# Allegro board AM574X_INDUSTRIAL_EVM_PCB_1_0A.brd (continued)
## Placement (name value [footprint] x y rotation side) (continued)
Q27  MMBT2907A  [SOT23-3-44M]  113.41 128.27 180 bottom
R1_1  DNI  [SM-7351-RES-0603]  179.31 7.63 90 top
R2  10K  [SM-7351-RES-0402]  127.89 64.85 0 top
R2_1  DNI  [SM-7351-RES-0402]  172.7 6.49 180 top
R3  22.1  [SM-7351-RES-0402]  182.02 96.6 0 bottom
R4  1M  [SM-7351-RES-0402]  77.6 82.38 270 top
R5  0  [SM-7351-RES-0402]  79.25 82.76 180 top
R6  0  [SM-7351-RES-0402]  133.73 74.07 0 top
R7  0  [SM-7351-RES-0402]  124.08 65.49 0 top
R8  0  [SM-7351-RES-0402]  124.08 69.3 0 top
R9  0  [SM-7351-RES-0402]  136.91 126.45 180 bottom
R10  10K  [SM-7351-RES-0402]  170.05 45.76 180 bottom
R11  100  [SM-7351-RES-0402]  168.15 53.55 0 bottom
R13  0  [SM-7351-RES-0402]  69.74 82.33 180 top
R14  0  [SM-7351-RES-0402]  130.43 114.76 270 top
R15  0  [SM-7351-RES-0402]  132.72 114.76 270 top
R16  1K  [SM-7351-RES-0402]  134.49 122.38 180 bottom
R17  1K  [SM-7351-RES-0402]  137.13 122.3 180 bottom
R18  10K  [SM-7351-RES-0402]  144.54 126.96 90 bottom
R19  0  [SM-7351-RES-0402]  142.49 140.54 90 top
R20  0  [SM-7351-RES-0402]  142.88 135.97 90 top
R21  1K  [SM-7351-RES-0402]  138.94 128.35 270 bottom
R22  10K  [SM-7351-RES-0402]  89.79 108.79 270 top
R23  0  [SM-7351-RES-0402]  101.85 112.48 270 top
R24  0  [SM-7351-RES-0402]  101.98 99.78 270 top
R25  0  [SM-7351-RES-0402]  98.68 108.79 270 top
R26  0  [SM-7351-RES-0402]  91.06 124.16 90 top
R27  0  [SM-7351-RES-0402]  91.06 108.79 270 top
R28  0  [SM-7351-RES-0402]  101.35 124.16 90 top
R29  0  [SM-7351-RES-0402]  97.41 124.16 90 top
R30  0  [SM-7351-RES-0402]  92.33 124.16 90 top
R31  0  [SM-7351-RES-0402]  101.85 114.51 270 top
R32  10K  [SM-7351-RES-0402]  124.71 40.51 0 top
R33  10K  [SM-7351-RES-0402]  108.84 40.51 180 top
R34  10K  [SM-7351-RES-0402]  124.71 38.48 0 top
R35  10K  [SM-7351-RES-0402]  108.84 39.5 180 top
R36  18.2K  [SM-7351-RES-0402]  124.59 42.75 180 top
R37  10K  [SM-7351-RES-0402]  124.71 39.5 0 top
R38  10K  [SM-7351-RES-0402]  108.84 37.46 180 top
R39  10K  [SM-7351-RES-0402]  124.71 37.46 0 top
R40  10K  [SM-7351-RES-0402]  108.84 38.48 180 top
R41  240  [SM-7351-RES-0402]  93.6 30.1 180 top
R42  240  [SM-7351-RES-0402]  124.08 30.1 180 top
R44  240  [SM-7351-RES-0402]  108.84 30.1 180 top
R45  10K  [SM-7351-RES-0402]  111.12 15.11 0 top
R46  49.9  [SM-7351-RES-0402]  127.51 31.5 180 bottom
R47  49.9  [SM-7351-RES-0402]  127.51 30.48 180 bottom
R48  10K  [SM-7351-RES-0402]  111.12 13.97 180 top
R49  47  [SM-7351-RES-0402]  124.08 29.59 180 bottom
R50  47  [SM-7351-RES-0402]  108.84 26.42 0 top
R51  47  [SM-7351-RES-0402]  108.71 30.35 0 bottom
R52  47  [SM-7351-RES-0402]  108.71 27.81 0 bottom
R53  47  [SM-7351-RES-0402]  117.22 21.72 90 bottom
R54  47  [SM-7351-RES-0402]  118.24 21.72 90 bottom
R55  47  [SM-7351-RES-0402]  119.25 21.72 90 bottom
R56  100K  [SM-7351-RES-0402]  108.2 11 270 top
R57  47  [SM-7351-RES-0402]  116.46 21.72 90 top
R58  47  [SM-7351-RES-0402]  114.17 21.72 90 bottom
R59  47  [SM-7351-RES-0402]  124.08 26.29 180 top
R60  47  [SM-7351-RES-0402]  116.2 21.72 90 bottom
R61  47  [SM-7351-RES-0402]  124.08 25.02 180 bottom
R62  47  [SM-7351-RES-0402]  113.16 21.72 90 top
R63  47  [SM-7351-RES-0402]  120.27 21.72 90 top
R64  47  [SM-7351-RES-0402]  114.17 21.72 90 top
R65  47  [SM-7351-RES-0402]  117.47 21.72 90 top
R66  47  [SM-7351-RES-0402]  124.08 31.88 180 top
R67  0  [SM-7351-RES-0402]  106.3 11.51 180 top
R68  47  [SM-7351-RES-0402]  121.54 21.72 90 bottom
R69  10  [SM-7351-RES-0402]  104.65 17.4 180 top
R70  47  [SM-7351-RES-0402]  115.32 21.72 90 top
R71  47  [SM-7351-RES-0402]  118.49 21.72 90 top
R72  47  [SM-7351-RES-0402]  115.19 21.72 90 bottom
R73  47  [SM-7351-RES-0402]  124.08 27.56 180 top
R74  47  [SM-7351-RES-0402]  120.4 21.72 90 bottom
R75  47  [SM-7351-RES-0402]  108.84 27.56 0 top
R76  2.2K  [SM-7351-RES-0402]  25.91 121.11 0 bottom
R77  0  [SM-7351-RES-0402]  22.48 136.48 90 bottom
R78  0  [SM-7351-RES-0402]  7.75 141.69 180 bottom
R79  DNI  [SM-7351-RES-0402]  38.25 110.75 90 top
R80  DNI  [SM-7351-RES-0402]  32.66 110.75 90 top
R81  DNI  [SM-7351-RES-0402]  35.46 110.75 90 top
R82  DNI  [SM-7351-RES-0402]  36.86 110.75 90 top
R83  0  [SM-7351-RES-0402]  24.77 112.73 270 bottom
R84  DNI  [SM-7351-RES-0402]  34.06 110.75 90 top
R85  DNI  [SM-7351-RES-0402]  31.27 110.75 90 top
R86  0  [SM-7351-RES-0402]  23.68 112.73 270 bottom
R87  DNI  [SM-7351-RES-0402]  87.38 102.19 90 top
R88  DNI  [SM-7351-RES-0402]  86.11 102.19 90 top
R89  0  [SM-7351-RES-0402]  7.24 119.72 180 bottom
R90  DNI  [SM-7351-RES-0402]  91.19 102.19 90 top
R91  DNI  [SM-7351-RES-0402]  89.92 102.19 90 top
R92  DNI  [SM-7351-RES-0402]  84.84 102.19 90 top
R93  0  [SM-7351-RES-0402]  6.48 132.03 270 bottom
R94  DNI  [SM-7351-RES-0402]  88.65 102.19 90 top
R95  DNI  [SM-7351-RES-0402]  22.86 110.7 270 bottom
R96  0  [SM-7351-RES-0402]  25.91 118.83 0 bottom
R97  0  [SM-7351-RES-0603]  23.49 123.78 270 top
R98  0  [SM-7351-RES-0402]  25.91 119.84 0 bottom
R99  49.9  [SM-7351-RES-0402]  17.84 123.53 0 bottom
R100  49.9  [SM-7351-RES-0402]  19.87 123.53 180 bottom
R101  49.9  [SM-7351-RES-0402]  22.61 127.21 90 bottom
R102  49.9  [SM-7351-RES-0402]  22.61 129.24 270 bottom
R103  4.87K  [SM-7351-RES-0402]  23.49 121.11 180 top
R104  2.2K  [SM-7351-RES-0402]  22.03 113.11 90 bottom
R105  DNI  [SM-7351-RES-0402]  86.11 114.13 270 top
R106  0  [SM-7351-RES-0402]  6.48 129.88 90 bottom
R107  10K  [SM-7351-RES-0402]  43.05 86.82 270 bottom
R108  2.2K  [SM-7351-RES-0402]  17.53 115.78 90 bottom
R109  2.2K  [SM-7351-RES-0402]  18.73 114.25 90 bottom
R110  2.2K  [SM-7351-RES-0402]  19.87 114.25 90 bottom
R111  2.2K  [SM-7351-RES-0402]  21.02 114.25 90 bottom
R112  0  [SM-7351-RES-0402]  44.7 87.33 0 bottom
R113  62  [SM-7351-RES-0402]  140.34 14.86 180 top
R114  0  [SM-7351-RES-0402]  141.61 10.41 0 top
R115  0  [SM-7351-RES-0402]  43.43 83.14 90 top
R116  2.2K  [SM-7351-RES-0402]  141.61 11.43 0 top
R117  0  [SM-7351-RES-0402]  45.97 83.14 90 top
R118  0  [SM-7351-RES-0402]  48.51 83.14 90 top
R119  0  [SM-7351-RES-0402]  51.05 83.14 90 top
R120  2.2K  [SM-7351-RES-0402]  29.59 93.17 270 top
R121  0  [SM-7351-RES-0402]  23.37 99.27 270 bottom
R122  0  [SM-7351-RES-0402]  7.7 117.55 180 bottom
R123  DNI  [SM-7351-RES-0402]  114.68 99.78 270 top
R124  DNI  [SM-7351-RES-0402]  118.49 99.9 270 top
R125  DNI  [SM-7351-RES-0402]  114.55 103.84 90 top
R126  DNI  [SM-7351-RES-0402]  119.63 103.84 90 top
R127  DNI  [SM-7351-RES-0402]  116.08 99.78 270 top
R128  DNI  [SM-7351-RES-0402]  117.47 99.9 270 top
R129  DNI  [SM-7351-RES-0402]  118.36 103.84 90 top
R130  DNI  [SM-7351-RES-0402]  117.09 103.84 90 top
R131  2.2K  [SM-7351-RES-0402]  27.69 95.33 270 top
R132  DNI  [SM-7351-RES-0402]  52.58 109.56 90 top
R133  DNI  [SM-7351-RES-0402]  58.17 109.56 90 top
R134  0  [SM-7351-RES-0402]  7.19 95.58 180 bottom
R135  DNI  [SM-7351-RES-0402]  59.56 109.56 90 top
R136  DNI  [SM-7351-RES-0402]  120.9 103.84 90 top
R137  DNI  [SM-7351-RES-0402]  115.82 103.84 90 top
R138  0  [SM-7351-RES-0603]  6.48 108.67 270 bottom
R139  DNI  [SM-7351-RES-0402]  56.77 109.56 90 top
R140  0  [SM-7351-RES-0402]  30.61 95.33 270 top
R141  0  [SM-7351-RES-0603]  29.34 101.55 270 bottom
R142  0  [SM-7351-RES-0402]  29.59 95.33 270 top
R143  49.9  [SM-7351-RES-0402]  24.38 106.89 270 top
R144  49.9  [SM-7351-RES-0402]  24.38 104.86 90 top
R145  49.9  [SM-7351-RES-0402]  24.38 102.82 270 top
R146  49.9  [SM-7351-RES-0402]  24.38 100.67 90 top
R147  4.87K  [SM-7351-RES-0402]  26.03 97.74 0 top
R148  DNI  [SM-7351-RES-0402]  55.37 109.56 90 top
R149  10K  [SM-7351-RES-0402]  186.72 83.14 180 bottom
R150  DNI  [SM-7351-RES-0402]  53.98 109.56 90 top
R151  0  [SM-7351-RES-0402]  6.43 105.74 90 bottom
R152  2.2K  [SM-7351-RES-0402]  37.39 100.16 0 top
R153  10K  [SM-7351-RES-0402]  33.15 89.74 90 bottom
R154  0  [SM-7351-RES-0402]  34.8 89.24 0 bottom
R155  2.2K  [SM-7351-RES-0402]  37.34 104.73 180 top
R156  2.2K  [SM-7351-RES-0402]  37.34 103.59 180 top
R157  2.2K  [SM-7351-RES-0402]  37.34 102.44 180 top
R158  2.2K  [SM-7351-RES-0402]  37.34 101.3 180 top
R159  2.2K  [SM-7351-RES-0402]  28.19 77.55 270 top
R160  0  [SM-7351-RES-0402]  23.37 75.14 270 bottom
R161  0  [SM-7351-RES-0402]  7.75 93.43 180 bottom
R162  0  [SM-7351-RES-0402]  124.08 82.76 180 top
R163  0  [SM-7351-RES-0402]  124.08 81.62 180 top
R164  0  [SM-7351-RES-0402]  124.08 83.9 180 top
R165  0  [SM-7351-RES-0402]  37.34 77.68 0 top
R166  0  [SM-7351-RES-0402]  37.34 78.82 0 top
R167  0  [SM-7351-RES-0402]  120.27 84.54 180 top
R168  0  [SM-7351-RES-0402]  120.27 82.25 180 top
R169  0  [SM-7351-RES-0402]  124.08 85.17 180 top
R170  0  [SM-7351-RES-0402]  37.34 81.11 0 top
R171  0  [SM-7351-RES-0402]  37.34 83.52 0 bottom
R172  0  [SM-7351-RES-0402]  7.24 71.46 180 bottom
R173  0  [SM-7351-RES-0402]  37.34 84.66 0 bottom
R174  0  [SM-7351-RES-0402]  37.34 85.81 0 bottom
R175  0  [SM-7351-RES-0402]  37.34 86.95 0 bottom
R176  0  [SM-7351-RES-0402]  6.48 83.77 270 bottom
R177  0  [SM-7351-RES-0402]  37.34 79.96 0 top
R178  0  [SM-7351-RES-0402]  124.08 80.35 180 top
R179  0  [SM-7351-RES-0402]  30.61 77.55 270 top
R180  0  [SM-7351-RES-0603]  29.34 83.77 270 bottom
R181  0  [SM-7351-RES-0402]  29.59 77.55 270 top
R182  49.9  [SM-7351-RES-0402]  24.38 89.11 270 top
R183  49.9  [SM-7351-RES-0402]  24.38 87.08 90 top
R184  49.9  [SM-7351-RES-0402]  24.38 85.04 270 top
R185  49.9  [SM-7351-RES-0402]  24.38 82.89 90 top
R186  4.87K  [SM-7351-RES-0402]  28.19 77.55 90 bottom
R187  2.2K  [SM-7351-RES-0402]  37.34 82.5 180 top
R188  0  [SM-7351-RES-0402]  120.27 78.06 180 top
R189  0  [SM-7351-RES-0402]  6.48 81.62 90 bottom
R190  10K  [SM-7351-RES-0402]  28.19 71.2 90 bottom
R191  2.2K  [SM-7351-RES-0402]  37.34 86.95 180 top
R192  2.2K  [SM-7351-RES-0402]  37.34 85.81 180 top
R193  2.2K  [SM-7351-RES-0402]  37.34 84.66 180 top
R194  2.2K  [SM-7351-RES-0402]  37.34 83.52 180 top
R195  0  [SM-7351-RES-0402]  29.84 70.69 0 bottom
R196  0  [SM-7351-RES-0402]  43.31 74.5 90 top
R197  0  [SM-7351-RES-0402]  45.85 74.5 90 top
R198  0  [SM-7351-RES-0402]  48.39 74.5 90 top
R199  0  [SM-7351-RES-0402]  50.93 74.5 90 top
R200  2.2K  [SM-7351-RES-0402]  28.19 52.79 270 top
R201  2.2K  [SM-7351-RES-0402]  29.59 50.63 270 top
R202  0  [SM-7351-RES-0402]  23.37 50.37 270 bottom
R203  0  [SM-7351-RES-0402]  7.75 68.66 180 bottom
R204  0  [SM-7351-RES-0402]  78.36 95.97 0 top
R205  0  [SM-7351-RES-0402]  78.36 98 0 top
R206  0  [SM-7351-RES-0402]  78.36 94.95 0 top
R207  0  [SM-7351-RES-0402]  78.36 93.93 0 top
R208  0  [SM-7351-RES-0402]  78.36 92.92 0 top
R209  0  [SM-7351-RES-0402]  37.34 52.91 0 top
R210  0  [SM-7351-RES-0402]  78.36 96.98 0 top
R211  0  [SM-7351-RES-0402]  37.34 54.06 0 top
R212  0  [SM-7351-RES-0402]  37.34 56.34 0 top
R213  0  [SM-7351-RES-0402]  37.34 58.76 0 bottom
R214  0  [SM-7351-RES-0402]  7.24 46.69 180 bottom
R215  0  [SM-7351-RES-0402]  37.34 59.9 0 bottom
R216  0  [SM-7351-RES-0402]  37.34 61.04 0 bottom
R217  0  [SM-7351-RES-0402]  37.34 62.18 0 bottom
R218  0  [SM-7351-RES-0603]  6.48 59.39 270 bottom
R219  0  [SM-7351-RES-0402]  37.34 55.2 0 top
R220  DNI  [SM-7351-RES-0402]  124.08 74.76 180 top
R221  0  [SM-7351-RES-0402]  30.61 52.79 270 top
R222  0  [SM-7351-RES-0603]  29.34 59.01 270 bottom
R223  0  [SM-7351-RES-0402]  29.59 52.79 270 top
R224  49.9  [SM-7351-RES-0402]  24.38 64.34 270 top
R225  49.9  [SM-7351-RES-0402]  24.38 62.31 90 top
R226  49.9  [SM-7351-RES-0402]  24.38 60.28 270 top
R227  49.9  [SM-7351-RES-0402]  24.38 58.12 90 top
R228  4.87K  [SM-7351-RES-0402]  28.19 52.79 90 bottom
R230  0  [SM-7351-RES-0402]  124.08 77.17 180 top
R231  0  [SM-7351-RES-0402]  6.48 56.6 270 bottom
R232  2.2K  [SM-7351-RES-0402]  37.34 57.74 0 bottom
R233  10K  [SM-7351-RES-0402]  28.19 46.44 90 bottom
R234  0  [SM-7351-RES-0402]  29.84 45.93 0 bottom
R235  2.2K  [SM-7351-RES-0402]  37.34 62.18 180 top
R236  2.2K  [SM-7351-RES-0402]  37.34 61.04 180 top
R237  2.2K  [SM-7351-RES-0402]  37.34 59.9 180 top
R238  2.2K  [SM-7351-RES-0402]  37.34 58.76 180 top
R239  220  [SM-7351-RES-0402]  9.53 4.7 180 bottom
R240  220  [SM-7351-RES-0402]  16.13 4.7 180 bottom
R241  0  [SM-7351-RES-0402]  9.53 3.64 180 bottom
R242  220  [SM-7351-RES-0402]  9.53 11.43 180 bottom
R243  0  [SM-7351-RES-0402]  16.13 3.64 180 bottom
R244  220  [SM-7351-RES-0402]  16.13 11.43 180 bottom
R245  100K  [SM-7351-RES-0402]  9.53 2.62 0 bottom
R246  100K  [SM-7351-RES-0402]  16.13 2.62 0 bottom
R247  0  [SM-7351-RES-0402]  9.53 10.37 0 bottom
R248  0  [SM-7351-RES-0402]  16.13 10.37 0 bottom
R249  220  [SM-7351-RES-0402]  9.53 8 180 bottom
R250  220  [SM-7351-RES-0402]  16.13 8 180 bottom
R251  100K  [SM-7351-RES-0402]  9.53 9.35 0 bottom
R252  100K  [SM-7351-RES-0402]  16.13 9.35 0 bottom
R253  0  [SM-7351-RES-0402]  9.53 6.94 0 bottom
R254  0  [SM-7351-RES-0402]  16.13 6.94 0 bottom
R255  100K  [SM-7351-RES-0402]  9.53 5.92 0 bottom
R256  100K  [SM-7351-RES-0402]  16.13 5.92 0 bottom
R257  0  [SM-7351-RES-0402]  159 142.83 270 top
R258  0  [SM-7351-RES-0402]  162.71 133.56 90 top
R259  10K  [SM-7351-RES-0402]  177.95 133.56 270 bottom
R260  0  [SM-7351-RES-0402]  161.54 142.83 90 top
R261  0  [SM-7351-RES-0402]  164.11 133.56 270 top
R262  0  [SM-7351-RES-0402]  165.38 133.56 90 top
R263  0  [SM-7351-RES-0402]  166.65 133.56 270 top
R264  0  [SM-7351-RES-0402]  167.79 133.56 90 top
R265  0  [SM-7351-RES-0402]  169.19 133.56 270 top
R267  0  [SM-7351-RES-0402]  174.27 133.56 270 top
R269  0  [SM-7351-RES-0402]  176.81 133.56 270 top
R271  0  [SM-7351-RES-0402]  179.35 133.56 270 top
R273  0  [SM-7351-RES-0402]  181.89 133.56 270 top
R274  0  [SM-7351-RES-0402]  180.62 133.56 90 top
R275  0  [SM-7351-RES-0402]  185.57 133.56 90 top
R276  22.1  [SM-7351-RES-0402]  163.83 144.02 0 bottom
R277  0  [SM-7351-RES-0402]  188.11 133.56 90 top
R278  0  [SM-7351-RES-0603]  29.29 115.5 270 bottom
R279  1.5K  [SM-7351-RES-0402]  41.15 116.41 180 top
R280  100K  [SM-7351-RES-0402]  38.99 110.7 0 bottom
R281  22.1  [SM-7351-RES-0402]  84.84 103.21 270 top
R282  22.1  [SM-7351-RES-0402]  86.11 103.21 270 top
R283  22.1  [SM-7351-RES-0402]  87.38 103.21 270 top
R284  22.1  [SM-7351-RES-0402]  88.65 103.21 270 top
R285  22.1  [SM-7351-RES-0402]  36.86 111.76 270 top
R286  22.1  [SM-7351-RES-0402]  89.92 103.21 270 top
R287  22.1  [SM-7351-RES-0402]  91.19 103.21 270 top
R288  22.1  [SM-7351-RES-0402]  38.25 111.76 270 top
R289  22.1  [SM-7351-RES-0402]  35.46 111.76 270 top
R290  22.1  [SM-7351-RES-0402]  34.06 111.76 270 top
R291  22.1  [SM-7351-RES-0402]  32.66 111.76 270 top
R292  22.1  [SM-7351-RES-0402]  31.27 111.76 270 top
R293  220  [SM-7351-RES-0402]  33.02 145.37 90 bottom
R294  0  [SM-7351-RES-0402]  39.55 113.95 270 top
R295  0  [SM-7351-RES-0402]  41.15 117.43 0 top
R296  220  [SM-7351-RES-0402]  34.16 145.37 90 bottom
R297  4.7K  [SM-7351-RES-0402]  41.15 118.45 0 top
R298  12.1K  [SM-7351-RES-0402]  41.15 124.54 0 top
R299  10K  [SM-7351-RES-0402]  35.48 113.95 270 top
R300  DNI  [SM-7351-RES-0402]  163.83 145.29 0 bottom
R301  10K  [SM-7351-RES-0402]  34.09 113.95 270 top
R304  1K  [SM-7351-RES-0402]  36.88 113.95 270 top
R305  1M  [SM-7351-RES-0402]  45.5 103.06 270 bottom
R306  10K  [SM-7351-RES-0402]  32.77 114 270 top
R308  0  [SM-7351-RES-0402]  45.5 105.1 270 bottom
R309  10K  [SM-7351-RES-0402]  31.5 114 270 top
R310  33  [SM-7351-RES-0402]  38 103.95 180 bottom
R312  0  [SM-7351-RES-0402]  43.81 103.59 270 top
R313  33  [SM-7351-RES-0402]  38 105.1 180 bottom
R314  0  [SM-7351-RES-0402]  42.8 103.59 270 top
R315  33  [SM-7351-RES-0402]  38 107 180 bottom
R317  1K  [SM-7351-RES-0402]  38.28 113.95 270 top
R319  1K  [SM-7351-RES-0402]  28.45 124.03 0 top
R321  1K  [SM-7351-RES-0402]  28.45 121.11 0 top
R322  0  [SM-7351-RES-0603]  50.67 112.22 270 bottom
R324  100K  [SM-7351-RES-0402]  60.71 110.7 0 bottom
R325  22.1  [SM-7351-RES-0402]  119.63 104.86 270 top
R326  22.1  [SM-7351-RES-0402]  114.55 104.86 270 top
R327  22.1  [SM-7351-RES-0402]  117.09 104.86 270 top
R328  22.1  [SM-7351-RES-0402]  59.56 110.57 270 top
R329  22.1  [SM-7351-RES-0402]  58.17 110.57 270 top
R330  22.1  [SM-7351-RES-0402]  120.9 104.86 270 top
R331  22.1  [SM-7351-RES-0402]  115.82 104.86 270 top
R332  22.1  [SM-7351-RES-0402]  118.36 104.86 270 top
R333  22.1  [SM-7351-RES-0402]  56.77 110.57 270 top
R334  22.1  [SM-7351-RES-0402]  55.37 110.57 270 top
R335  22.1  [SM-7351-RES-0402]  53.98 110.57 270 top
R336  22.1  [SM-7351-RES-0402]  52.58 110.57 270 top
R337  220  [SM-7351-RES-0402]  54.74 145.37 90 bottom
R338  0  [SM-7351-RES-0402]  60.83 112.98 270 top
R339  0  [SM-7351-RES-0402]  62.99 117.05 0 top
R340  220  [SM-7351-RES-0402]  55.88 145.37 90 bottom
R341  12.1K  [SM-7351-RES-0402]  61.72 125.18 90 top
R342  4.7K  [SM-7351-RES-0402]  62.99 118.45 0 top
R343  10K  [SM-7351-RES-0402]  56.77 112.98 270 top
R345  10K  [SM-7351-RES-0402]  55.37 112.98 270 top
R348  1K  [SM-7351-RES-0402]  58.17 112.98 270 top
R349  1M  [SM-7351-RES-0402]  59.18 99.52 270 bottom
R351  0  [SM-7351-RES-0402]  59.18 101.68 270 bottom
R352  10K  [SM-7351-RES-0402]  53.98 112.98 270 top
R353  10K  [SM-7351-RES-0402]  52.58 112.98 270 top
R354  33  [SM-7351-RES-0402]  52.07 96.09 270 bottom
R356  DNI  [SM-7351-RES-0402]  57.78 106.13 90 bottom
R357  33  [SM-7351-RES-0402]  50.8 96.09 270 bottom
R358  DNI  [SM-7351-RES-0402]  56.64 106.13 90 bottom
R359  33  [SM-7351-RES-0402]  53.21 106.13 90 bottom
R361  1K  [SM-7351-RES-0402]  59.56 112.98 270 top
R363  1K  [SM-7351-RES-0402]  50.16 124.03 0 top
R364  10K  [SM-7351-RES-0402]  50.16 120.48 0 top
R366  10K  [SM-7351-RES-0402]  178.31 54.95 270 top
R367  0  [SM-7351-RES-0402]  127.89 75.27 180 top
R368  1.2K  [SM-7351-CAP-0805]  178.97 58.17 0 bottom
R369  0  [SM-7351-RES-0402]  127.89 76.28 180 top
R370  1.2K  [SM-7351-CAP-0805]  178.97 55.63 0 bottom
R371  0  [SM-7351-RES-0402]  85.47 94.36 0 top
R372  1.2K  [SM-7351-CAP-0805]  178.97 53.09 0 bottom
R373  1.2K  [SM-7351-CAP-0805]  178.97 48.01 0 bottom
R374  1.2K  [SM-7351-CAP-0805]  178.97 50.55 0 bottom
R375  1.2K  [SM-7351-CAP-0805]  178.97 45.47 0 bottom
R376  1.2K  [SM-7351-CAP-0805]  178.97 42.93 0 bottom
R377  0  [SM-7351-RES-0402]  121.54 71.33 180 top
R378  1.2K  [SM-7351-CAP-0805]  178.98 40.39 0 bottom
R379  49.9  [SM-7351-CAP-0805]  185.29 75.01 270 bottom
R380  0  [SM-7351-RES-0402]  177.29 74.12 270 bottom
R381  0  [SM-7351-RES-0402]  178.69 74.12 270 bottom
R382  25K  [SM-7351-RES-0603]  182.37 73.87 0 bottom
R383  2.2K  [SM-7351-RES-0402]  127.89 69.3 0 top
R384  2.2K  [SM-7351-RES-0402]  127.89 72.47 0 top
R385  0  [SM-7351-RES-0402]  127.89 71.46 180 top
R386  150  [SM-7351-RES-0402]  176.15 37.46 0 top
R387  0  [SM-7351-RES-0402]  127.89 70.31 180 top
R388  150  [SM-7351-RES-0402]  176.15 35.31 0 top
R389  150  [SM-7351-RES-0402]  176.15 33.15 0 top
R390  150  [SM-7351-RES-0402]  176.15 30.99 0 top
R391  150  [SM-7351-RES-0402]  176.15 28.83 0 top
R392  150  [SM-7351-RES-0402]  176.15 26.67 0 top
R393  0  [SM-7351-RES-0402]  124.08 72.34 0 top
R394  0  [SM-7351-RES-0402]  124.08 70.69 0 top
R395  150  [SM-7351-RES-0402]  176.15 24.51 0 top
R396  150  [SM-7351-RES-0402]  176.15 22.35 0 top
R397  10K  [SM-7351-RES-0402]  95.25 148.37 180 bottom
R398  10K  [SM-7351-RES-0402]  95.25 149.39 180 bottom
R399  10K  [SM-7351-RES-0402]  86.49 148.63 0 bottom
R400  10K  [SM-7351-RES-0402]  86.49 147.61 0 bottom
R401  10K  [SM-7351-RES-0402]  95.25 147.36 180 bottom
R402  0  [SM-7351-RES-0402]  78.36 100.03 0 top
R403  0  [SM-7351-RES-0402]  78.36 103.08 0 top
R404  0  [SM-7351-RES-0402]  78.36 104.09 0 top
R405  0  [SM-7351-RES-0402]  78.36 105.11 0 top
R406  0  [SM-7351-RES-0402]  78.36 101.05 0 top
R407  0  [SM-7351-RES-0402]  78.36 102.06 0 top
R408  470K  [SM-7351-RES-0402]  96.9 138.08 90 bottom
R409  0  [SM-7351-RES-0402]  78.36 99.01 0 top
R410  0  [SM-7351-RES-0402]  75.69 141.31 270 bottom
R411  0  [SM-7351-RES-0402]  74.55 141.31 270 bottom
R412  10K  [SM-7351-RES-0402]  77.22 147.66 0 top
R413  10  [SM-7351-RES-0402]  74.68 148.34 270 bottom
R414  47K  [SM-7351-RES-0402]  75.82 148.34 270 bottom
R415  2.0  [SM-7351-RES-0603]  76.96 145.16 90 bottom
R416  0  [SM-7351-RES-0402]  77.22 148.93 0 top
R417  10K  [SM-7351-RES-0402]  76.83 141.31 270 bottom
R418  0  [SM-7351-RES-0402]  56.22 88.29 0 bottom
R419  100K  [SM-7351-RES-0402]  154.36 103.47 270 bottom
R420  10K  [SM-7351-RES-0402]  56.22 87.23 180 bottom
R421  DNI  [SM-7351-RES-0402]  10.67 32 90 bottom
R422  4.7K  [SM-7351-RES-0402]  181.89 92.66 0 bottom
R423  4.7K  [SM-7351-RES-0402]  177.8 92.16 180 top
R424  1.62M  [SM-7351-RES-0402]  157.66 106.27 90 bottom
R425  10K  [SM-7351-RES-0402]  145.16 135.97 90 top
R426  22.1  [SM-7351-RES-0402]  124.08 73.74 180 top
R427  180K  [SM-7351-RES-0402]  157.66 104.11 90 bottom
R428  0  [SM-7351-RES-0402]  146.3 136.02 90 top
R429  100  [SM-7351-RES-0402]  187.1 91.14 270 bottom
R430  10K  [SM-7351-RES-0402]  144.02 135.97 90 top
R431  10K  [SM-7351-RES-0402]  142.75 125.18 0 bottom
R432  10K  [SM-7351-RES-0402]  142.24 121.75 0 bottom
R433  4.7K  [SM-7351-RES-0402]  182.02 95.2 0 bottom
R434  DNI  [SM-7351-RES-0402]  101.22 108.92 90 top
R435  18K  [SM-7351-RES-0402]  108.84 113.37 90 top
R436  18K  [SM-7351-RES-0402]  104.27 108.92 90 top
R437  DNI  [SM-7351-RES-0402]  106.81 113.37 90 top
R438  DNI  [SM-7351-RES-0402]  107.82 113.37 90 top
R439  DNI  [SM-7351-RES-0402]  103.25 108.92 90 top
R440  DNI  [SM-7351-RES-0402]  102.23 108.92 90 top
R441  DNI  [SM-7351-RES-0402]  110.87 113.37 90 top
R442  18K  [SM-7351-RES-0402]  109.86 113.37 90 top
R443  DNI  [SM-7351-RES-0402]  109.35 108.92 90 top
R444  DNI  [SM-7351-RES-0402]  110.36 108.92 90 top
R445  DNI  [SM-7351-RES-0402]  111.38 108.92 90 top
R446  DNI  [SM-7351-RES-0402]  112.39 108.92 90 top
R447  DNI  [SM-7351-RES-0402]  105.66 108.92 90 top
R448  DNI  [SM-7351-RES-0402]  113.41 108.92 90 top
R449  18K  [SM-7351-RES-0402]  106.68 108.92 90 top
R450  4.7K  [SM-7351-RES-0402]  186.59 88.47 180 bottom
R451  0  [SM-7351-RES-0402]  144.53 99.52 180 top
R453  10K  [SM-7351-RES-0402]  101.6 108.92 270 bottom
R454  DNI  [SM-7351-RES-0402]  108.84 113.37 270 bottom
R455  DNI  [SM-7351-RES-0402]  104.65 108.92 270 bottom
R456  10K  [SM-7351-RES-0402]  106.81 113.37 270 bottom
R457  10K  [SM-7351-RES-0402]  107.82 113.37 270 bottom
R458  10K  [SM-7351-RES-0402]  103.63 108.92 270 bottom
R459  10K  [SM-7351-RES-0402]  102.62 108.92 270 bottom
R460  10K  [SM-7351-RES-0402]  110.87 113.37 270 bottom
R461  DNI  [SM-7351-RES-0402]  109.86 113.37 270 bottom
R462  10K  [SM-7351-RES-0402]  109.35 108.92 270 bottom
R463  10K  [SM-7351-RES-0402]  110.36 108.92 270 bottom
R464  10K  [SM-7351-RES-0402]  111.38 108.92 270 bottom
R465  10K  [SM-7351-RES-0402]  112.39 108.92 270 bottom
R466  10K  [SM-7351-RES-0402]  105.66 108.92 270 bottom
R467  10K  [SM-7351-RES-0402]  113.41 108.92 270 bottom
R468  DNI  [SM-7351-RES-0402]  106.68 108.92 270 bottom
R472  0  [SM-7351-RES-0603]  171.12 80.01 0 bottom
R473  0  [SM-7351-RES-0402]  156.46 73.53 0 bottom
R474  0  [SM-7351-RES-0402]  155.63 76.33 0 top
R475  0  [SM-7351-RES-0402]  159.56 71.51 90 top
R476  0  [SM-7351-RES-0402]  162.74 68.97 90 top
R477  0  [SM-7351-RES-0402]  163.63 71.51 90 top
R478  0  [SM-7351-RES-0402]  164.9 71.51 90 top
R479  12K  [SM-7351-RES-0402]  156.01 81.41 180 top
R480  0  [SM-7351-RES-0402]  160.71 71.51 90 top
R481  0  [SM-7351-RES-0402]  161.59 68.97 90 top
R482  0  [SM-7351-RES-0402]  165.91 71.51 90 top
R483  0  [SM-7351-RES-0402]  166.93 71.51 90 top
R484  4.7K  [SM-7351-RES-0402]  164.9 69.09 90 top
R485  10K  [SM-7351-RES-0402]  155.63 77.35 180 top
R486  0  [SM-7351-RES-0402]  113.03 62.74 270 top
R487  0  [SM-7351-RES-0402]  111.89 62.74 270 top
R489  0  [SM-7351-RES-0402]  169.09 71.51 90 top
R491  4.7K  [SM-7351-RES-0402]  163.12 88.78 90 top
R492  0  [SM-7351-RES-0402]  165.28 88.78 270 top
R493  220  [SM-7351-RES-0402]  161.98 88.78 90 top
R494  10K  [SM-7351-RES-0402]  164.13 88.78 270 top
R495  2.2K  [SM-7351-RES-0402]  162.61 85.98 270 bottom
R496  10K  [SM-7351-RES-0402]  163.63 85.98 90 bottom
R497  0  [SM-7351-RES-0402]  79.38 87.46 180 top
R498  DNI  [SM-7351-RES-0402]  61.21 64.14 270 bottom
R499  0  [SM-7351-RES-0402]  76.83 78.61 0 top
R500  DNI  [SM-7351-RES-0402]  62.36 64.14 270 bottom
R502  33  [SM-7351-RES-0402]  171.7 21.29 180 bottom
R503  120  [SM-7351-RES-0402]  155.58 11.13 90 bottom
R504  33  [SM-7351-RES-0402]  172.85 18.75 180 bottom
R505  49.9K  [SM-7351-RES-0402]  86.87 129.24 180 top
R506  49.9K  [SM-7351-RES-0402]  86.87 126.45 180 top
R507  49.9K  [SM-7351-RES-0402]  86.87 125.3 180 top
R508  49.9K  [SM-7351-RES-0402]  89.53 131.91 90 top
R509  49.9K  [SM-7351-RES-0402]  88.39 131.91 90 top
R510  49.9K  [SM-7351-RES-0402]  86.87 128.1 180 top
R511  49.9K  [SM-7351-RES-0402]  86.87 123.65 180 top
R512  49.9K  [SM-7351-RES-0402]  86.87 122.51 180 top
R513  49.9K  [SM-7351-RES-0402]  95.25 104.98 270 bottom
R514  0  [SM-7351-RES-0402]  16.13 13.92 180 bottom
R515  100K  [SM-7351-RES-0402]  16.13 16.21 0 bottom
R539  10K  [SM-7351-RES-0402]  53.72 38.23 270 top
R542  10K  [SM-7351-RES-0402]  49.53 38.23 270 top
R543  10K  [SM-7351-RES-0402]  50.67 38.23 270 top
R544  10K  [SM-7351-RES-0402]  52.58 38.23 270 top
R545  10K  [SM-7351-RES-0402]  54.86 38.23 90 top
R546  10K  [SM-7351-RES-0402]  33.91 34.63 0 bottom
R547  DNI  [SM-7351-RES-0402]  21.84 42.88 0 bottom
R548  10K  [SM-7351-RES-0402]  29.46 31.58 270 bottom
R549  10K  [SM-7351-RES-0402]  30.48 31.58 270 bottom
R550  0  [SM-7351-RES-0402]  30.73 31.58 270 top
R551  10K  [SM-7351-RES-0402]  23.88 14.22 180 bottom
R553  10K  [SM-7351-RES-0402]  24.38 3.17 270 bottom
R554  0  [SM-7351-RES-0402]  174.12 75.01 270 top
R555  0  [SM-7351-RES-0402]  175.13 75.01 270 top
R556  DNI  [SM-7351-RES-0402]  124.08 64.47 0 top
R557  0  [SM-7351-RES-0402]  85.47 90.51 0 top
R558  0  [SM-7351-RES-0402]  65.15 22.86 180 top
R559  0  [SM-7351-RES-0402]  65.15 23.88 0 top
R560  DNI  [SM-7351-RES-0402]  58.8 12.45 90 top
R561  DNI  [SM-7351-RES-0402]  56.52 12.45 270 top
R562  DNI  [SM-7351-RES-0402]  57.66 12.45 90 top
R563  DNI  [SM-7351-RES-0402]  127.89 66.88 0 top
R564  0  [SM-7351-RES-0402]  120.27 85.81 0 top
R565  0  [SM-7351-RES-0402]  127.89 86.82 180 top
R566  0  [SM-7351-RES-0402]  157.23 98.63 0 bottom
R567  0  [SM-7351-RES-0402]  157.23 97.62 0 bottom
R568  0  [SM-7351-RES-0402]  28.45 31.58 270 bottom
R569  0  [SM-7351-RES-0402]  81.91 84.28 180 bottom
R570  10K  [SM-7351-RES-0402]  143.51 130.76 0 bottom
R571  10K  [SM-7351-RES-0402]  147.83 114.76 270 top
R572  0  [SM-7351-RES-0402]  131.44 114.76 90 top
R573  0  [SM-7351-RES-0402]  106.68 8.25 270 top
R574  0  [SM-7351-RES-0402]  112.9 99.78 270 bottom
R575  0  [SM-7351-RES-0402]  112.9 103.84 270 top
R576  0  [SM-7351-RES-0402]  106.81 105.66 90 top
R577  100K  [SM-7351-RES-0402]  114.43 8.89 180 top
R578  100K  [SM-7351-RES-0402]  114.43 7.62 0 top
R579  2.2K  [SM-7351-RES-0402]  130.18 10.16 180 top
R580  100  [SM-7351-RES-0402]  60.2 37.21 0 top
R581  100  [SM-7351-RES-0402]  78.61 77.17 90 top
R582  0  [SM-7351-RES-0402]  120.27 65.99 180 top
R583  0  [SM-7351-RES-0402]  110.74 62.74 90 top
R584  0  [SM-7351-RES-0402]  92.46 102.19 270 top
R585  0  [SM-7351-RES-0402]  157.23 96.6 0 bottom
R586  0  [SM-7351-RES-0402]  143.76 96.22 180 bottom
R587  0  [SM-7351-RES-0402]  181.89 93.68 0 bottom
R588  0  [SM-7351-RES-0402]  132.72 114.68 90 bottom
R589  220  [SM-7351-RES-0402]  9.53 18.16 180 bottom
R590  0  [SM-7351-RES-0402]  9.53 17.1 0 bottom
R591  100K  [SM-7351-RES-0402]  9.53 16.08 0 bottom
R592  100K  [SM-7351-RES-0402]  16.13 19.64 0 bottom
R593  0  [SM-7351-RES-0402]  16.13 20.66 0 bottom
R594  0  [SM-7351-RES-0402]  9.53 20.53 0 bottom
R595  100K  [SM-7351-RES-0402]  9.53 19.51 0 bottom
R596  220  [SM-7351-RES-0402]  9.53 14.86 180 bottom
R597  100K  [SM-7351-RES-0402]  16.13 12.91 0 bottom
R598  0  [SM-7351-RES-0402]  16.13 17.23 0 bottom
R599  100K  [SM-7351-RES-0402]  9.53 12.78 0 bottom
R600  0  [SM-7351-RES-0402]  9.53 13.8 180 bottom
R601  220  [SM-7351-RES-0402]  9.53 21.59 180 bottom
R602  220  [SM-7351-RES-0402]  16.13 18.29 180 bottom
R603  220  [SM-7351-RES-0402]  16.13 21.72 180 bottom
R604  220  [SM-7351-RES-0402]  16.13 14.99 180 bottom
R605  0  [SM-7351-RES-0402]  127.89 94.57 180 top
R606  0  [SM-7351-RES-0402]  127.89 95.59 180 top
R607  0  [SM-7351-RES-0402]  131.44 101.17 0 top
R608  0  [SM-7351-RES-0402]  131.44 85.55 0 top
R609  0  [SM-7351-RES-0402]  131.44 88.98 0 top
R610  0  [SM-7351-RES-0402]  131.44 102.44 0 top
R611  0  [SM-7351-RES-0402]  131.44 98.13 0 top
R612  0  [SM-7351-RES-0402]  131.44 103.71 0 top
R613  0  [SM-7351-RES-0402]  127.89 92.2 0 top
R614  0  [SM-7351-RES-0402]  127.89 89.36 0 top
R615  0  [SM-7351-RES-0402]  131.44 92.79 0 top
R616  0  [SM-7351-RES-0402]  131.44 96.22 0 top
R617  0  [SM-7351-RES-0402]  124.08 96.35 0 top
R618  0  [SM-7351-RES-0402]  131.44 94.95 0 top
R619  0  [SM-7351-RES-0402]  131.44 99.4 0 top
R620  0  [SM-7351-RES-0402]  131.44 91.52 0 top
R621  0  [SM-7351-RES-0402]  124.08 95.08 0 top
R622  0  [SM-7351-RES-0402]  124.08 92.54 0 top
R623  0  [SM-7351-RES-0402]  124.08 91.27 0 top
R624  0  [SM-7351-RES-0402]  124.08 93.81 0 top
R625  0  [SM-7351-RES-0402]  131.44 86.82 0 top
R626  0  [SM-7351-RES-0402]  124.08 87.46 0 top
R627  0  [SM-7351-RES-0402]  124.08 88.73 0 top
R628  0  [SM-7351-RES-0402]  124.08 90 0 top
R630  100  [SM-7351-RES-0402]  78.61 122.13 270 bottom
R631  100  [SM-7351-RES-0402]  77.34 120.6 270 bottom
R632  100  [SM-7351-RES-0402]  77.34 123.65 90 bottom
R633  100  [SM-7351-RES-0402]  78.61 119.08 90 bottom
R634  0  [SM-7351-RES-0402]  120.27 87.08 180 top
R635  0  [SM-7351-RES-0402]  127.89 88.09 180 top
R636  0  [SM-7351-RES-0402]  124.08 86.31 180 top
R637  10K  [SM-7351-RES-0402]  157.23 99.65 180 bottom
R638  0  [SM-7351-RES-0402]  165.74 5.03 180 top
R639  0.05ohm  [SM_RES_LVK12]  64.26 75.39 90 top
R640  0.05ohm  [SM_RES_LVK12]  105.28 134.83 180 top
R641  0.01ohm  [SM_RES_LVK12]  112.65 134.7 180 top
R642  0.02ohm  [SM_RES_LVK12]  120.78 134.7 180 top
R643  0  [SM-7351-RES-0402]  74.93 73.66 0 top
R644  10K  [SM-7351-RES-0402]  86.61 107.4 90 top
R645  10K  [SM-7351-RES-0402]  93.85 103.25 90 top
R646  51K  [SM-7351-RES-0402]  157.39 117.9 90 top
R647  158K  [SM-7351-RES-0402]  161.07 121.58 90 top
R648  18.2K  [SM-7351-RES-0402]  161.07 119.42 90 top
R649  10K  [SM-7351-RES-0402]  45.59 38.23 90 top
R650  100  [SM-7351-RES-0402]  44.58 38.23 270 top
R652  0  [SM-7351-RES-0402]  50.29 24.64 270 top
R653  0  [SM-7351-RES-0402]  51.31 24.64 270 top
R654  10K  [SM-7351-RES-0402]  56.01 24.64 270 top
R655  100  [SM-7351-RES-0402]  54.99 24.64 90 top
R656  0  [SM-7351-RES-0603]  151.13 120.22 0 top
R657  0  [SM-7351-RES-0402]  137.01 128.34 0 bottom
R658  0  [SM-7351-RES-0402]  138.81 134.7 270 bottom
R659  0  [SM-7351-RES-0402]  85.47 89.49 0 top
R660  0  [SM-7351-RES-0402]  92.84 98.25 270 top
R661  0  [SM-7351-RES-0402]  119.63 74.25 180 bottom
R662  0  [SM-7351-RES-0402]  120.27 80.85 180 top
R663  0  [SM-7351-RES-0402]  105.54 113.37 270 top
R664  0  [SM-7351-RES-0402]  108.58 99.78 270 bottom
R665  0  [SM-7351-RES-0402]  104.52 113.37 270 top
R666  0  [SM-7351-RES-0402]  119.63 73.23 180 bottom
R669  0  [SM-7351-RES-0402]  113.54 99.78 90 top
R670  0  [SM-7351-RES-0402]  112.27 99.78 90 top
R671  0  [SM-7351-RES-0402]  111.38 99.78 90 bottom
R672  0  [SM-7351-RES-0402]  111.63 103.84 90 top
R673  0  [SM-7351-RES-0402]  127.89 85.81 180 top
R674  0  [SM-7351-RES-0402]  120.27 79.08 0 bottom
R675  0  [SM-7351-RES-0402]  127.89 83.27 180 top
R676  0  [SM-7351-RES-0402]  127.89 84.54 180 top
R677  0  [SM-7351-RES-0402]  179.1 80.73 180 bottom
R678  0  [SM-7351-RES-0402]  70.99 117.18 180 bottom
R679  0  [SM-7351-RES-0402]  158.78 117.9 270 top
R680  10K  [SM-7351-RES-0402]  73.53 114.89 270 bottom
R681  19.6K  [SM-7351-RES-0402]  73.53 112.86 90 bottom
R682  0  [SM-7351-RES-0402]  68.45 23.75 90 top
R683  0  [SM-7351-RES-0402]  69.47 23.75 90 top
R684  0  [SM-7351-RES-0402]  120.27 67.01 0 top
R685  0  [SM-7351-RES-0402]  124.08 68.28 180 top
R686  0  [SM-7351-RES-0402]  100.84 99.78 270 top
R687  100  [SM-7351-RES-0402]  77.34 117.68 90 bottom
R688  0  [SM-7351-RES-0402]  103.38 99.78 270 top
R689  0  [SM-7351-RES-0402]  104.27 121.75 270 top
R690  0  [SM-7351-RES-0402]  104.65 99.78 270 top
R691  0  [SM-7351-RES-0402]  105.92 99.78 270 top
R692  0  [SM-7351-RES-0402]  103.89 102.44 270 top
R693  220  [SM-7351-RES-0402]  72.64 105.54 180 bottom
R694  0  [SM-7351-RES-0402]  81.03 100.28 90 bottom
R695  100K  [SM-7351-RES-0402]  79.76 100.28 90 bottom
R696  220  [SM-7351-RES-0402]  76.07 105.54 180 bottom
R697  100K  [SM-7351-RES-0402]  76.45 100.28 90 bottom
R698  0  [SM-7351-RES-0402]  77.47 100.28 270 bottom
R699  220  [SM-7351-RES-0402]  79.5 105.54 180 bottom
R700  100K  [SM-7351-RES-0402]  72.9 100.28 90 bottom
R701  0  [SM-7351-RES-0402]  74.04 100.28 90 bottom
R702  220  [SM-7351-RES-0402]  68.83 103.5 180 bottom
R703  0  [SM-7351-RES-0402]  70.74 91.14 90 bottom
R704  100K  [SM-7351-RES-0402]  69.6 91.14 90 bottom
R705  220  [SM-7351-RES-0402]  69.22 89.41 180 bottom
R706  100K  [SM-7351-RES-0402]  69.47 84.03 90 bottom
R707  0  [SM-7351-RES-0402]  70.61 84.03 270 bottom
R708  220  [SM-7351-RES-0402]  67.18 95.12 180 bottom
R709  100K  [SM-7351-RES-0402]  69.09 98.25 90 bottom
R710  0  [SM-7351-RES-0402]  70.23 98.25 90 bottom
R711  DNI  [SM-7351-RES-0402]  132.46 101.17 180 top
R712  DNI  [SM-7351-RES-0402]  132.46 96.22 180 top
R713  DNI  [SM-7351-RES-0402]  125.09 93.81 180 top
R714  DNI  [SM-7351-RES-0402]  132.46 85.55 180 top
R715  DNI  [SM-7351-RES-0402]  132.46 88.98 180 top
R716  DNI  [SM-7351-RES-0402]  132.46 102.44 180 top
R717  DNI  [SM-7351-RES-0402]  132.46 103.71 180 top
R718  DNI  [SM-7351-RES-0402]  132.46 98.13 180 top
R719  DNI  [SM-7351-RES-0402]  132.46 92.79 180 top
R720  DNI  [SM-7351-RES-0402]  125.09 96.35 180 top
R721  DNI  [SM-7351-RES-0402]  132.46 99.4 180 top
R722  DNI  [SM-7351-RES-0402]  132.46 91.52 180 top
R723  DNI  [SM-7351-RES-0402]  132.46 94.95 180 top
R724  DNI  [SM-7351-RES-0402]  125.09 91.27 180 top
R725  DNI  [SM-7351-RES-0402]  132.46 86.82 180 top
R726  DNI  [SM-7351-RES-0402]  125.09 88.73 180 top
R727  DNI  [SM-7351-RES-0402]  125.09 90 180 top
R728  DNI  [SM-7351-RES-0402]  125.09 87.46 180 top
R729  100  [SM-7351-RES-0402]  161.54 7.96 90 top
R730  100  [SM-7351-RES-0402]  182.02 97.62 180 bottom
R731  100  [SM-7351-RES-0402]  184.68 95.2 90 bottom
R732  0  [SM-7351-RES-0402]  106.93 99.78 270 top
R733  0  [SM-7351-RES-0402]  106.05 102.44 270 top
R734  0  [SM-7351-RES-0402]  105.03 102.44 270 top
R735  0  [SM-7351-RES-0402]  107.06 102.44 90 top
R736  0  [SM-7351-RES-0402]  82.68 92.46 180 top
R737  0  [SM-7351-RES-0402]  82.68 91.44 180 top
R738  0  [SM-7351-RES-0402]  85.47 88.39 180 top
R739  0  [SM-7351-RES-0402]  131.06 59.31 270 top
R740  0  [SM-7351-RES-0402]  132.21 59.31 270 top
R741  10K  [SM-7351-RES-0402]  95 135.84 90 bottom
R742  0  [SM-7351-RES-0603]  140.34 126.07 270 bottom
R743  0  [SM-7351-RES-0402]  103.38 143.72 270 top
R744  0  [SM-7351-RES-0402]  120.9 99.9 270 top
R746  DNI  [SM-7351-RES-0402]  114.55 99.9 270 bottom
R747  DNI  [SM-7351-RES-0402]  118.36 97.74 90 bottom
R748  DNI  [SM-7351-RES-0402]  30.61 93.17 90 top
R749  DNI  [SM-7351-RES-0402]  119.51 101.17 90 bottom
R750  DNI  [SM-7351-RES-0402]  118.24 101.17 90 bottom
R751  DNI  [SM-7351-RES-0402]  114.55 101.94 90 bottom
R752  DNI  [SM-7351-RES-0402]  59.56 107.52 90 top
R753  DNI  [SM-7351-RES-0402]  52.58 107.52 90 top
R754  240  [SM-7351-RES-0402]  143.13 40.47 90 bottom
R755  240  [SM-7351-RES-0402]  143.13 55.71 90 bottom
R756  47  [SM-7351-RES-0402]  151 59.14 180 top
R757  47  [SM-7351-RES-0402]  144.02 70.95 270 bottom
R758  47  [SM-7351-RES-0402]  143 70.95 270 top
R759  47  [SM-7351-RES-0402]  151 66.25 180 top
R760  47  [SM-7351-RES-0402]  151 67.26 180 top
R761  47  [SM-7351-RES-0402]  151 65.23 180 top
R762  47  [SM-7351-RES-0402]  151 64.22 180 bottom
R763  47  [SM-7351-RES-0402]  151 61.17 180 top
R764  47  [SM-7351-RES-0402]  151 60.15 180 top
R765  47  [SM-7351-RES-0402]  146.05 70.95 270 bottom
R766  47  [SM-7351-RES-0402]  147.07 70.95 270 bottom
R767  47  [SM-7351-RES-0402]  148.08 70.95 270 bottom
R768  47  [SM-7351-RES-0402]  151 60.15 180 bottom
R769  47  [SM-7351-RES-0402]  151 66.25 180 bottom
R770  47  [SM-7351-RES-0402]  151 61.17 180 bottom
R771  47  [SM-7351-RES-0402]  151 62.18 180 top
R772  47  [SM-7351-RES-0402]  151 63.2 180 top
R773  47  [SM-7351-RES-0402]  151 63.2 180 bottom
R774  47  [SM-7351-RES-0402]  151 62.18 180 bottom
R775  47  [SM-7351-RES-0402]  151 65.23 180 bottom
R776  47  [SM-7351-RES-0402]  151 59.14 180 bottom
R777  47  [SM-7351-RES-0402]  145.03 70.95 270 bottom
R778  47  [SM-7351-RES-0402]  143 70.95 270 bottom
R779  47  [SM-7351-RES-0402]  151 64.22 180 top
R780  49.9  [SM-7351-RES-0402]  140.97 70.95 270 top
R781  49.9  [SM-7351-RES-0402]  141.99 70.95 270 top
R782  100K  [SM-7351-RES-0402]  163.45 57.1 0 bottom
R783  0  [SM-7351-RES-0402]  163.07 59.01 90 bottom
R784  10  [SM-7351-RES-0402]  157.23 60.66 90 bottom
R785  10K  [SM-7351-RES-0402]  160.66 54.18 90 bottom
R786  10K  [SM-7351-RES-0402]  159.51 54.18 270 bottom
R787  0  [SM-7351-RES-0402]  82.93 88.27 0 top
R788  100  [SM-7351-RES-0402]  8.76 44.32 0 bottom
R790  10K  [SM-7351-RES-0402]  16.89 42.88 90 top
R791  10K  [SM-7351-RES-0402]  18.41 46.82 180 top
R792  0  [SM-7351-RES-0402]  56.22 86.08 0 bottom
R793  20.5K  [SM-7351-RES-0402]  124.59 43.9 0 top
R794  0  [SM-7351-RES-0402]  140.69 122.38 270 bottom
R795  0  [SM-7351-RES-0402]  68.33 20.4 90 bottom
R796  0  [SM-7351-RES-0402]  65.66 23.07 90 bottom
R797  0  [SM-7351-RES-0402]  120.27 80.73 180 bottom
R798  10K  [SM-7351-RES-0402]  165.74 3.89 0 top
R799  10K  [SM-7351-RES-0402]  100.33 124.16 90 top
R800  10K  [SM-7351-RES-0402]  85.47 93.34 180 top
R801  0.05ohm  [SM_RES_LVK12]  65.53 53.8 0 top
R802  0  [SM-7351-RES-0402]  85.47 95.38 180 top
R803  0  [SM-7351-RES-0402]  85.47 91.52 180 top
R804  DNI  [SM-7351-RES-0402]  130.68 68.79 0 top
R805  DNI  [SM-7351-RES-0402]  130.68 70.31 0 top
R806  47  [SM-7351-RES-0402]  124.08 27.56 180 bottom
R807  47  [SM-7351-RES-0402]  144.91 55.71 90 bottom
R808  10K  [SM-7351-RES-0402]  8.76 43.18 0 bottom
R809  0  [SM-7351-RES-0402]  93.98 98.3 270 top
R810  10K  [SM-7351-RES-0402]  146.3 138.43 90 top
R811  10K  [SM-7351-RES-0402]  153.8 140.59 90 top
R812  1M  [SM-7351-RES-0402]  30.23 18.41 180 bottom
R813  1M  [SM-7351-RES-0402]  5.46 31.5 0 top
R814  10K  [SM-7351-RES-0402]  138.3 113.03 90 bottom
R854  0  [SM-7351-RES-0402]  145.67 125.98 270 bottom
R861  0  [SM-7351-RES-0402]  129.92 143 270 top
R862  0  [SM-7351-RES-0402]  133.22 143 270 top
R863  0  [SM-7351-RES-0402]  135.26 143 270 top
R864  0  [SM-7351-RES-0402]  137.29 143 270 top
R894  499  [SM-7351-RES-0402]  36.07 96.65 90 bottom
R895  10K  [SM-7351-RES-0402]  35.43 94.61 180 bottom
R896  DNI  [SM-7351-RES-0402]  34.92 96.65 90 bottom
R897  24.3K  [SM-7351-RES-0402]  38.1 91.31 180 bottom
R898  499  [SM-7351-RES-0402]  113.92 125.48 180 bottom
R899  10K  [SM-7351-RES-0402]  115.95 124.84 270 bottom
R900  DNI  [SM-7351-RES-0402]  113.92 124.33 180 bottom
R901  24.3K  [SM-7351-RES-0402]  119.25 127.51 270 bottom
R902  10K  [SM-7351-RES-0402]  164.85 149.1 270 bottom
R903  22.1  [SM-7351-RES-0402]  172.97 143 180 bottom
R905  DNI  [SM-7351-RES-0402]  163.83 146.56 180 bottom
R906  DNI  [SM-7351-RES-0402]  136.27 98.81 180 top
R907  DNI  [SM-7351-RES-0402]  137.03 90.93 180 top
R908  DNI  [SM-7351-RES-0402]  128.91 98.17 0 top
R909  DNI  [SM-7351-RES-0402]  127.89 91.19 0 top
R910  DNI  [SM-7351-RES-0402]  136.27 101.85 180 top
R911  DNI  [SM-7351-RES-0402]  129.29 103.76 0 top
R912  10K  [SM-7351-RES-0402]  124.08 25.02 180 top
R913  10K  [SM-7351-RES-0402]  149.61 70.48 180 top
R914  10K  [SM-7351-RES-0402]  165.99 52.45 180 bottom
R915  DNI  [SM-7351-RES-0402]  157.61 42.04 0 bottom
R916  100  [SM-7351-RES-0402]  170.05 42.93 0 bottom
R917  10K  [SM-7351-RES-0402]  166.24 46.1 90 bottom
R918  DNI  [SM-7351-RES-0402]  157.61 44.96 0 bottom
R919  DNI  [SM-7351-RES-0402]  157.61 46.74 0 bottom
R920  0  [SM-7351-RES-0402]  157.61 47.75 0 bottom
R921  0  [SM-7351-RES-0402]  157.61 41.02 0 bottom
R922  0  [SM-7351-RES-0402]  157.61 43.94 0 bottom
R923  0  [SM-7351-RES-0402]  66.93 79.63 180 top
R924  0  [SM-7351-RES-0402]  74.93 74.68 180 top
R925  0  [SM-7351-RES-0402]  66.93 81.41 180 top
R926  0  [SM-7351-RES-0402]  63.5 64.14 270 bottom
R927  DNI  [SM-7351-RES-0402]  79.88 89.15 270 top
R928  DNI  [SM-7351-RES-0402]  96.01 103.25 90 top
R929  DNI  [SM-7351-RES-0402]  95 103.25 270 top
R930  DNI  [SM-7351-RES-0402]  80.9 86.49 0 bottom
R931  0  [SM-7351-RES-0402]  80.9 85.34 0 bottom
R932  DNI  [SM-7351-RES-0402]  95 97.66 270 bottom
R933  0  [SM-7351-RES-0402]  92.08 97.66 270 bottom
R934  DNI  [SM-7351-RES-0402]  139.17 122.3 0 bottom
SCKT1  DNI  [SCK-SG-BGA-6334]  102.23 81.99 270 top
SW1  B3SL  [SW_B3SL-1022P]  166.88 44.15 180 top
SW2  B3SL  [SW_B3SL-1022P]  166.88 53.42 180 top
SW3  B3SL  [SW_B3SL-1022P]  166.88 62.44 180 top
TP1  TP  [TH_TP_5002]  175.92 129.88 0 top
TP1_1  DNI  [TH_TP_5002]  177.72 14 90 top
TP2  TP1mm  [TP_SMD1MMCIRCLE]  137.54 109.56 0 top
TP3  TP1mm  [TP_SMD1MMCIRCLE]  137.54 107.27 0 top
TP6  TP1mm  [TP_SMD1MMCIRCLE]  139.32 107.27 0 top
TP7  TP1mm  [TP_SMD1MMCIRCLE]  131.95 107.7 0 top
TP8  TP  [TH_TP_5002]  80.26 149.86 0 top
TP9  TP  [TH_TP_5002]  187.86 120.6 0 top
TP10  TP  [TH_TP_5002]  75.22 2.67 0 top
TP11  TP  [TH_TP_5002]  2.67 14.1 0 top
TP16  TP1mm  [TP_SMD1MMCIRCLE]  43.56 119.84 0 top
TP17  TP1mm  [TP_SMD1MMCIRCLE]  63.25 120.1 0 top
TP18  TP1mm  [TP_SMD1MMCIRCLE]  172.77 76.71 0 top
TP19  TP1mm  [TP_SMD1MMCIRCLE]  69.09 79.63 0 top
TP20  TP1mm  [TP_SMD1MMCIRCLE]  51.69 40.51 0 top
TP21  TP1mm  [TP_SMD1MMCIRCLE]  148.08 138.26 0 top
TP22  TP1mm  [TP_SMD1MMCIRCLE]  126.49 78.06 0 top
TP23  TP1mm  [TP_SMD1MMCIRCLE]  128.4 78.06 0 top
TP24  TP1mm  [TP_SMD1MMCIRCLE]  158.55 95.38 0 top
U1  AM5749ABZXEA  [BGA23X23-760-117M]  102.23 81.62 270 top
U1_1  DNI  [X2SON1X1-4-16M]  174.99 8.9 270 top
U2  SN74LVC1G07  [U_5_DCK]  166.88 42.96 0 bottom
U3  TPS6590375ZWSR  [BGA12X12-169-55M]  139.45 125.94 0 top
U4  S25FL256S  [SOIC_16PIN_DW]  95.5 116.41 180 top
U5  MT41K256M16HA  [BGA9X14-96]  85.98 31.88 0 top
U6  MT41K256M16HA  [BGA9X14-96]  116.46 31.88 0 top
U7  MT41K256M16HA  [BGA9X14-96]  101.22 31.88 0 top
U8  TPS51200  [DRCPSO_10PIN]  107.82 14.73 180 top
U9  TLK105L  [QFN5X5-32-39M]  21.34 118.7 0 bottom
U13  TLK105L  [QFN5X5-32-39M]  31.5 100.41 270 top
U15  TLK105L  [QFN5X5-32-39M]  31.5 82.63 270 top
U17  TLK105L  [QFN5X5-32-39M]  31.5 57.87 270 top
U18  PicoHaptics 304-100  [PICO_304-100]  140.84 17.65 180 top
U19  SN74LVC1G04  [SC70-5-43M]  187.22 85.81 90 bottom
U21  KSZ9031RN  [QFN7X7-48]  35.18 120.86 270 top
U22  SN74LVC1G07  [U_5_DCK]  35.81 110.06 270 bottom
U23  CDCE913  [TSSOP5X4-14-47M]  41.94 103.45 90 bottom
U24  KSZ9031RN  [QFN7X7-48]  56.9 120.86 270 top
U25  CDCE913  [TSSOP5X4-14-47M]  55.88 100.67 90 bottom
U26  SN74LVC1G07  [U_5_DCK]  57.53 110.06 270 bottom
U28  SN74LVC1G07  [U_5_DCK]  178.94 57.99 0 top
U30  TPD6E001  [U_10_RSE]  90.8 147.86 90 bottom
U32  TPS61081DRC  [U_10_DRC]  74.04 144.61 0 bottom
U33  CAT24C256W  [SOIC_8]  10.03 26.29 180 bottom
U34  SN74LVC1G00DCK  [U_5_DCK]  166.42 82.3 180 bottom
U35  SN74LVC1G07  [U_5_DCK]  159.89 75.06 90 bottom
U36  TPD2E001DRLR  [U_5_DRL]  182.27 14.1 180 top
U37  FT2232HL  [LQFP64PIN]  164.39 80.14 0 top
U38  93LC56B  [SOIC_8]  165.1 93.3 90 bottom
U39  DNI SN74LVC1G07  [U_5_DCK]  60.58 67.18 180 bottom
U40  R1Z-3.305HP  [SMD15X11-6-374M]  164.59 23.32 0 top
U41  ISO1050  [SO9X6-8-191M]  163.45 20.02 270 bottom
U43  EMMC16G  [BGA11X13-153-39M]  95.63 126.7 270 bottom
U44  74LVC1G125  [SC70-5-43M]  56.9 40.64 270 top
U45  CDCM9102  [QFN5X5-32TI-39M]  29.59 36.4 180 bottom
U46  TPD12S016  [PW_24PIN_TSSOP]  64.64 18.16 180 top
U47  DNI SN74LVC1G07  [U_5_DCK]  125.48 46.23 90 top
U48  TPD1E10B06  [TPD1E10B06-2L]  170.31 53.55 0 bottom
U49  TPD1E10B06  [TPD1E10B06-2L]  170.56 41.18 270 bottom
U50  TPD1E10B06  [TPD1E10B06-2L]  160.91 60.41 180 top
U52  TPS76650  [SOIC_8]  97.79 10.41 90 bottom
U62  TPS63010  [U_20_DSBGA]  155.37 106.14 90 bottom
U63  SN74AVC4T245  [U_16_PW]  172.77 85.09 90 bottom
U64  TPD2EUSB30DRTR  [SOT1X1-3-20M]  43.05 19.43 270 top
U65  SN74AVC2T244  [SON2X1-8-16M]  173.99 71.68 90 top
U66  TPS2065D  [U_8_D]  26.29 8.89 180 bottom
U68  SN74LVC1G08  [SM-SO-SC70-5]  42.42 89.62 180 bottom
U69  SN74LVC1G08  [SM-SO-SC70-5]  31.12 90.12 180 bottom
U70  SN74LVC1G08  [SM-SO-SC70-5]  26.16 71.68 180 bottom
U71  SN74LVC1G08  [SM-SO-SC70-5]  26.16 46.82 180 bottom
U72  SN65HVS882  [U_28_PWP]  181.89 68.2 0 bottom
U73  TPIC2810  [U_16_D]  168.15 34.37 0 bottom
U74  ISO1176T  [U_16_DW]  122.3 8.25 90 top
U75  SN74AVC2T244  [SON2X1-8-16M]  171.04 65.11 90 bottom
U76  TPS71712  [SMDSC70-5]  147.57 100.16 270 top
U77  SN65HVD78D  [SOIC_8]  177.17 8.84 0 bottom
U78  SN74LVC1G07  [SC70-5-43M]  187.1 94.19 90 bottom
U79  TPS61085  [MSOP3X3-8-43M]  158.4 122.59 90 top
U80  TPD1E10B06  [TPD1E10B06-2L]  92.2 8.51 180 top
U81  TPD1E10B06  [TPD1E10B06-2L]  94.61 8.51 0 top
U82  TPD1E10B06  [TPD1E10B06-2L]  160.78 11.43 180 top
U83  TPD1E10B06  [TPD1E10B06-2L]  163.2 11.43 0 top
U84  TPD1E10B06  [TPD1E10B06-2L]  96.9 135.04 270 top
U85  SN74LVC1G08  [SM-SO-SC70-5]  56.87 46.2 180 top
U86  LP38693ADJ  [SOT-223-5]  68.33 112.86 180 bottom
U87  TPD1E10B06  [TPD1E10B06-2L]  158.37 13.34 0 bottom
U88  TPD1E10B06  [TPD1E10B06-2L]  156.21 13.34 180 bottom
U89  TC358778  [BGA7X7-80-39M]  150.5 95.97 90 bottom
U90  MT41K256M16HA  [BGA9X14-96]  140.84 48.09 270 bottom
U91  MT41K256M16HA  [BGA9X14-96]  140.84 63.33 270 bottom
U92  TPS51200  [DRCPSO_10PIN]  159.89 57.49 90 bottom
U93  TPD4S012  [U_6_DRY]  6.6 40.59 270 top
U94  TPS2051BD  [U_8_D]  20.83 41.99 180 top
U95  TPD4E05U06  [USON2X1-10-22M]  39.75 19.05 90 bottom
U96  SN74LVC1G07  [SC70-5-43M]  150.11 141.73 0 top
U97  SN74LVC1G07  [U_5_DCK]  164.34 50.04 90 bottom
U98  SN74LVC1G08  [SM-SO-SC70-5]  163.58 43.94 0 bottom
X1  20.000 MHZ  [OSC7X5-71M]  169.93 147.57 0 bottom
Y1  20MHz  [XTAL2X3-30M]  73.91 82.38 0 top
Y2  16.384MHz  [XTAL3225-39M]  136.27 138 180 top
Y3  25MHz  [SM_OSC_ABM3]  49.18 103.19 270 bottom
Y4  25MHz  [SM_OSC_ABM3]  62.86 99.65 270 bottom
Y5  12MHz  [SM_OSC_ABM3]  151.43 84.33 270 top
Y6  32.768KHz MC-306  [MC-306]  72.26 88.09 180 top
Y7  25MHz  [ASF_SMD3_2X5MM]  21.72 40.21 270 bottom

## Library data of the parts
C1 C2 = 1C_24pFCapacitor50V5%SMD0402: Tolerance: TOLERANCE; User Part Number: USERPART#
C1_1 C2_1 C23 C316 C421 C459 = 1C_1uFCapacitor50V10%0603
C3 C7-C12 C14-C17 C28-C32 C34-C43 C48-C51 C55-C63 C65-C79 C81 C105 C112-C115 C118 C120 C127 C130 C137 C139 C142 C144 C151 C152 C165 C169-C171 C186 C190-C192 C195 C207 C210 C214 C216 C219-C221 C225-C230 C232-C236 C238-C240 C242 C248 C251 C255-C258 C261-C264 C267 C308-C310 C315 C319 C321 C322 C324 C326-C332 C334-C339 C341-C346 C348 C349 C351-C353 C355-C360 C362-C365 C367-C374 C376-C381 C385 C386 C388 C389 C391 C394 C400 C401 C403-C406 C408-C410 C420 C422-C430 C443 C444 C448 C451 C453 C469 C470 C480-C482 C485-C491 C493-C502 C506-C509 C511-C520 C524 C547 C548 C550-C553 C564 C567 C569 C571-C577 = 1C_0.01uFCapacitor16V10%0402: Tolerance: TOLERANCE; User Part Number: USERPART#
C4 C5 C209 C265 C286-C300 C350 C407 C442 C445-C447 C484 C565 C568 = GRT155R61E105KE01D: Tolerance: TOLERANCE
C6 C13 C22 C88 C91 C92 C95-C97 C110 C125 C136 C149 C154 C156 C159 C161 C163 C168 C175 C177 C180 C182 C184 C189 C215 C222 C266 C305-C307 C317 C320 C333 C340 C347 C354 C361 C375 C384 C387 C395 C396 C413 C414 C433 C458 C483 C532 C534-C536 C540 C541 = 1C_10uFCapacitor16V10%0805
C20 C21 C44-C47 C53 C54 C80 C82 C83 C85 C87 C89 C90 C93 C94 C98-C100 C102-C104 C107-C109 C111 C116 C117 C119 C122-C124 C126 C128 C129 C132-C135 C138 C140 C141 C143 C145 C147 C148 C150 C153 C155 C160 C162 C164 C174 C176 C181 C183 C185 C211 C213 C223 C245 C252 C313 C314 C390 C393 C415 C417 C436-C439 C454-C457 C460 C477 C478 C503-C505 C521-C523 C525-C531 C537-C539 C542 C549 C557 C559 C563 C566 C570 = C0402C104J4RACTU: Tolerance: TOLERANCE
C24 C411 C412 C440 C441 = 1C_100uFCapacitor16V20%ElecPoly
C25 C26 = C0402C270J5GACTU: Tolerance: TOLERANCE
C27 C166 C167 C187 C188 C303 C304 C431 C432 C434 C449 C556 = C1005X7R1H104K050BE: Tolerance: TOLERANCE
C33 C52 C64 C418 C419 C492 C510 = 1C_22uFCapacitor16V10%0805
C84 C86 C196 C543 C544 C558 C560 = 1C_0.001uFCapacitor50V5%0402: Tolerance: TOLERANCE; User Part Number: USERPART#
C101 C533 = 1C_10pFCapacitor50V1%smd0402: Tolerance: TOLERANCE; User Part Number: USERPART#
C106 C121 C131 C146 = 1C_4700pFCapacitor50V10%0402: Tolerance: TOLERANCE; User Part Number: USERPART#
C157 C158 C178 C179 = 1C_47uFCapacitor16V20%1206
C172 C173 C193 C194 C243 C244 = CGA2B2C0G1H180J050BA: Tolerance: TOLERANCE
C197-C204 = C1005X7R1H223K050BE: Tolerance: TOLERANCE
C205 C208 C224 C464-C468 C471 C472 C479 C578 = 1C_2.2uF16V10%SMD0805
C206 C435 = C3216X5R1H106K160AB
C212 C217 C231 C237 C241 C272-C275 C281-C285 C416 C546 = 1C_4.7uFCapacitor16V10%0603
C218 = C2012X5R1H475M125AB
C246 C247 = 1C_15pFCapacitor50V10%smd0402: Tolerance: TOLERANCE; User Part Number: USERPART#
C249 C250 = C1608X5R1C335K080AC
C253 C254 = 1C_100pFCapacitor16V10%0402: Tolerance: TOLERANCE; User Part Number: USERPART#
C268-C271 C276-C280 = 1C_47uFCapacitor10V20%SMD1206
C301 C302 C318 C382 C383 C392 C399 C402 C562 = 1C_2.2uFCapacitor6.3V20%X5R0402: Tolerance: TOLERANCE; User Part Number: USERPART#
C311 C545 = T495D157K010ATE100
C323 C325 = 4.7uFCapacitor16V20%Tant
C450 C452 = 1C_10uFCapacitor6.3V20%0603
C461 C462 = 1C_10uFCapacitor35V10%0805
C463 = 1C_1.1nFCapacitor50V5%0603
